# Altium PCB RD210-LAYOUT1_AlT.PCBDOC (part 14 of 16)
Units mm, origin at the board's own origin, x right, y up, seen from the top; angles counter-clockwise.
Board outline 330 x 300 mm, 6 copper layers (TOP, Mid-Layer 1, Mid-Layer 2, Mid-Layer 3, Mid-Layer 4, BOTTOM), stack 1.422 mm thick; 981 components, 463 nets, 2326 pads, 12534 vias.
Unrouted connection lines stored in the file: 6.
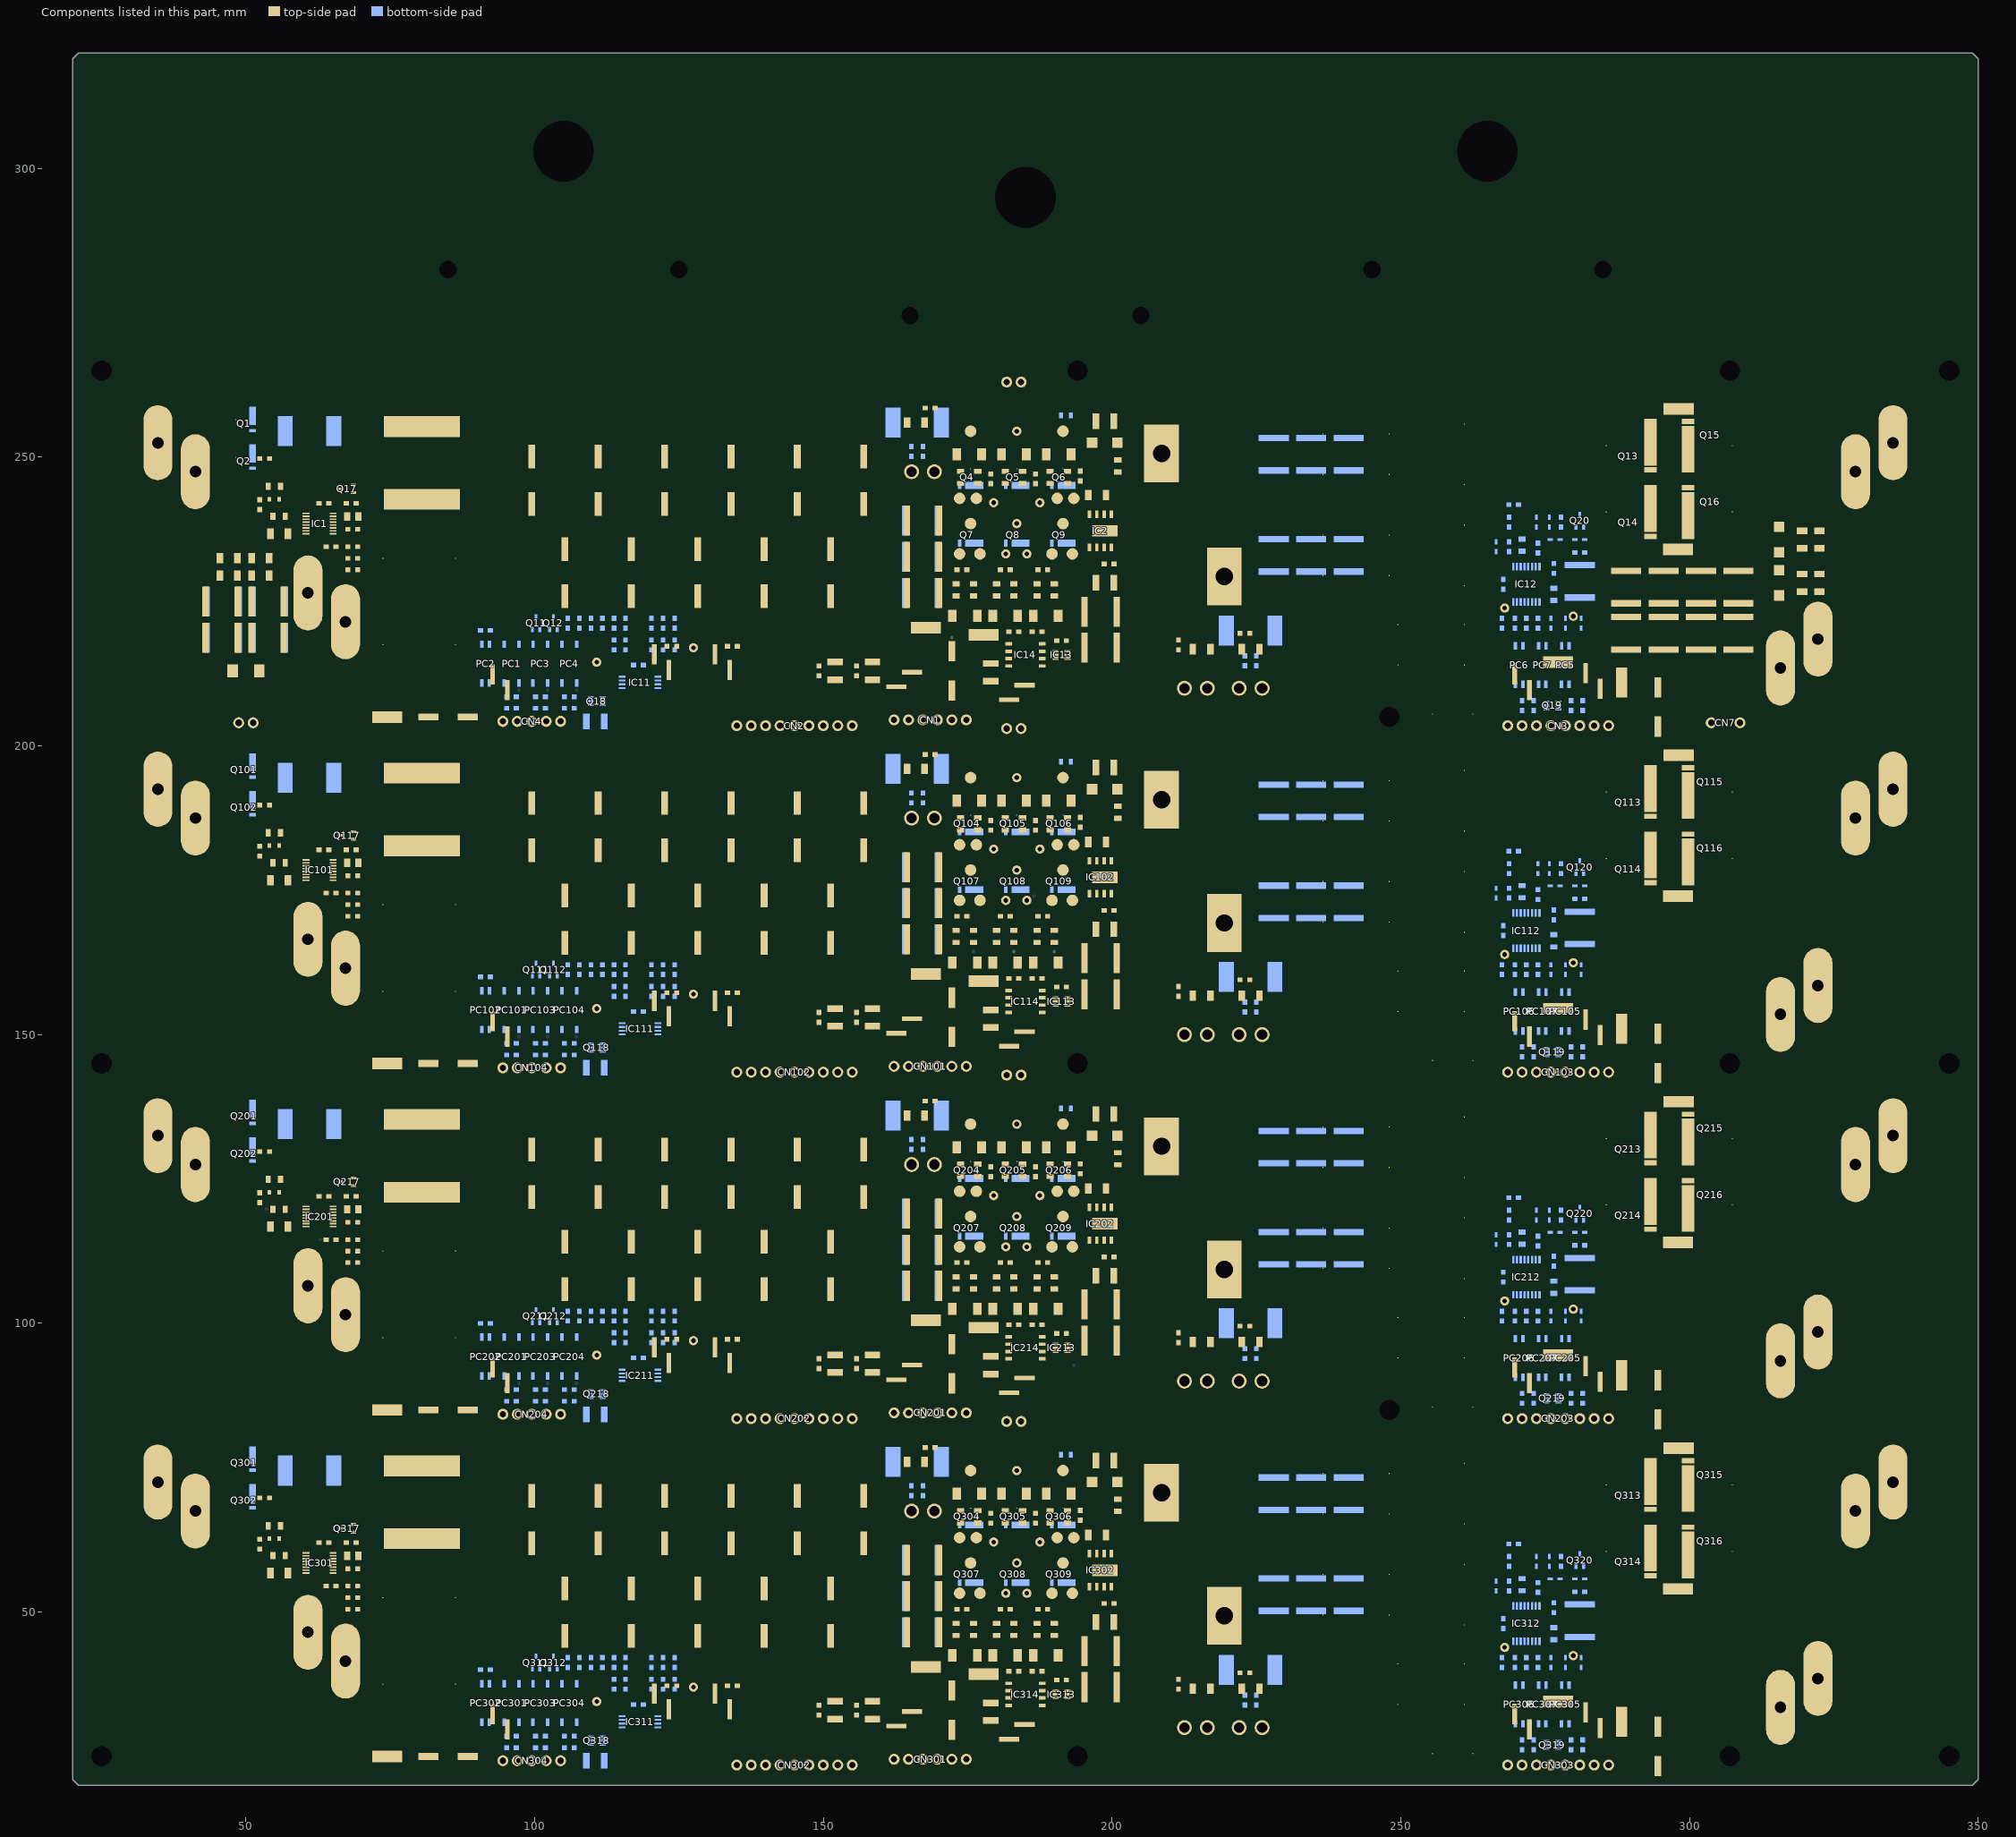
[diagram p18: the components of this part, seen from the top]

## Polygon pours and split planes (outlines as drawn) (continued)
no net on Bottom Overlay "BOTTOMOVERLAY797" (solid, pour order 0): 265.6,234.6 265.6,235.1 266.1,235.1 266.1,234.75 266.9,234.75 266.9,235.1 267.4,235.1 267.4,234.6
no net on Bottom Overlay "BOTTOMOVERLAY798" (solid, pour order 0): 281.1,234.85 281.1,236.65 281.6,236.65 281.6,236.15 281.25,236.15 281.25,235.35 281.6,235.35 281.6,234.85
no net on Bottom Overlay "BOTTOMOVERLAY799" (solid, pour order 0): 272.6,238.15 272.6,238.65 274.4,238.65 274.4,238.15 273.9,238.15 273.9,238.5 273.1,238.5 273.1,238.15
no net on Bottom Overlay "BOTTOMOVERLAY800" (solid, pour order 0): 265.6,174.6 265.6,175.1 266.1,175.1 266.1,174.75 266.9,174.75 266.9,175.1 267.4,175.1 267.4,174.6
no net on Bottom Overlay "BOTTOMOVERLAY801" (solid, pour order 0): 281.1,174.85 281.1,176.65 281.6,176.65 281.6,176.15 281.25,176.15 281.25,175.35 281.6,175.35 281.6,174.85
no net on Bottom Overlay "BOTTOMOVERLAY802" (solid, pour order 0): 272.85,178.15 272.85,178.65 274.65,178.65 274.65,178.15 274.15,178.15 274.15,178.5 273.35,178.5 273.35,178.15
no net on Bottom Overlay "BOTTOMOVERLAY803" (solid, pour order 0): 265.6,114.6 265.6,115.1 266.1,115.1 266.1,114.75 266.9,114.75 266.9,115.1 267.4,115.1 267.4,114.6
no net on Bottom Overlay "BOTTOMOVERLAY804" (solid, pour order 0): 281.1,114.85 281.1,116.65 281.6,116.65 281.6,116.15 281.25,116.15 281.25,115.35 281.6,115.35 281.6,114.85
no net on Bottom Overlay "BOTTOMOVERLAY805" (solid, pour order 0): 272.6,118.15 272.6,118.65 274.4,118.65 274.4,118.15 273.9,118.15 273.9,118.5 273.1,118.5 273.1,118.15
no net on Bottom Overlay "BOTTOMOVERLAY806" (solid, pour order 0): 265.6,54.6 265.6,55.1 266.1,55.1 266.1,54.75 266.9,54.75 266.9,55.1 267.4,55.1 267.4,54.6
no net on Bottom Overlay "BOTTOMOVERLAY807" (solid, pour order 0): 281.1,54.85 281.1,56.65 281.6,56.65 281.6,56.15 281.25,56.15 281.25,55.35 281.6,55.35 281.6,54.85
no net on Top Paste "TOPPASTE808" (solid, pour order 0): 282.85,248.45 282.85,251.75 285.35,251.75 285.35,248.45
no net on Top Paste "TOPPASTE809" (solid, pour order 0): 282.85,252.25 282.85,255.55 285.35,255.55 285.35,252.25
no net on Top Paste "TOPPASTE810" (solid, pour order 0): 285.85,252.25 285.85,255.55 288.65,255.55 288.65,252.25
no net on Top Paste "TOPPASTE811" (solid, pour order 0): 285.85,248.45 285.85,251.75 288.65,251.75 288.65,248.45
no net on Top Paste "TOPPASTE812" (solid, pour order 0): 292.15,248.55 292.15,249.45 294.35,249.45 294.35,248.55
no net on Top Paste "TOPPASTE813" (solid, pour order 0): 292.15,249.75 292.15,250.65 294.35,250.65 294.35,249.75
no net on Top Paste "TOPPASTE814" (solid, pour order 0): 292.15,250.95 292.15,251.85 294.35,251.85 294.35,250.95
no net on Top Paste "TOPPASTE815" (solid, pour order 0): 292.15,253.35 292.15,254.25 294.35,254.25 294.35,253.35
no net on Top Paste "TOPPASTE816" (solid, pour order 0): 292.15,254.55 292.15,255.45 294.35,255.45 294.35,254.55
no net on Top Paste "TOPPASTE817" (solid, pour order 0): 292.15,255.75 292.15,256.65 294.35,256.65 294.35,255.75
no net on Top Paste "TOPPASTE818" (solid, pour order 0): 282.85,236.95 282.85,240.25 285.35,240.25 285.35,236.95
no net on Top Paste "TOPPASTE819" (solid, pour order 0): 282.85,240.75 282.85,244.05 285.35,244.05 285.35,240.75
no net on Top Paste "TOPPASTE820" (solid, pour order 0): 285.85,240.75 285.85,244.05 288.65,244.05 288.65,240.75
no net on Top Paste "TOPPASTE821" (solid, pour order 0): 285.85,236.95 285.85,240.25 288.65,240.25 288.65,236.95
no net on Top Paste "TOPPASTE822" (solid, pour order 0): 292.15,237.05 292.15,237.95 294.35,237.95 294.35,237.05
no net on Top Paste "TOPPASTE823" (solid, pour order 0): 292.15,238.25 292.15,239.15 294.35,239.15 294.35,238.25
no net on Top Paste "TOPPASTE824" (solid, pour order 0): 292.15,239.45 292.15,240.35 294.35,240.35 294.35,239.45
no net on Top Paste "TOPPASTE825" (solid, pour order 0): 292.15,241.85 292.15,242.75 294.35,242.75 294.35,241.85
no net on Top Paste "TOPPASTE826" (solid, pour order 0): 292.15,243.05 292.15,243.95 294.35,243.95 294.35,243.05
no net on Top Paste "TOPPASTE827" (solid, pour order 0): 292.15,244.25 292.15,245.15 294.35,245.15 294.35,244.25
no net on Top Paste "TOPPASTE828" (solid, pour order 0): 307.65,252.25 307.65,255.55 310.15,255.55 310.15,252.25
no net on Top Paste "TOPPASTE829" (solid, pour order 0): 307.65,248.45 307.65,251.75 310.15,251.75 310.15,248.45
no net on Top Paste "TOPPASTE830" (solid, pour order 0): 304.35,248.45 304.35,251.75 307.15,251.75 307.15,248.45
no net on Top Paste "TOPPASTE831" (solid, pour order 0): 304.35,252.25 304.35,255.55 307.15,255.55 307.15,252.25
no net on Top Paste "TOPPASTE832" (solid, pour order 0): 298.65,254.55 298.65,255.45 300.85,255.45 300.85,254.55
no net on Top Paste "TOPPASTE833" (solid, pour order 0): 298.65,253.35 298.65,254.25 300.85,254.25 300.85,253.35
no net on Top Paste "TOPPASTE834" (solid, pour order 0): 298.65,252.15 298.65,253.05 300.85,253.05 300.85,252.15
no net on Top Paste "TOPPASTE835" (solid, pour order 0): 298.65,249.75 298.65,250.65 300.85,250.65 300.85,249.75
no net on Top Paste "TOPPASTE836" (solid, pour order 0): 298.65,248.55 298.65,249.45 300.85,249.45 300.85,248.55
no net on Top Paste "TOPPASTE837" (solid, pour order 0): 298.65,247.35 298.65,248.25 300.85,248.25 300.85,247.35
no net on Top Paste "TOPPASTE838" (solid, pour order 0): 307.65,240.75 307.65,244.05 310.15,244.05 310.15,240.75
no net on Top Paste "TOPPASTE839" (solid, pour order 0): 307.65,236.95 307.65,240.25 310.15,240.25 310.15,236.95
no net on Top Paste "TOPPASTE840" (solid, pour order 0): 304.35,236.95 304.35,240.25 307.15,240.25 307.15,236.95
no net on Top Paste "TOPPASTE841" (solid, pour order 0): 304.35,240.75 304.35,244.05 307.15,244.05 307.15,240.75
no net on Top Paste "TOPPASTE842" (solid, pour order 0): 298.65,243.05 298.65,243.95 300.85,243.95 300.85,243.05
no net on Top Paste "TOPPASTE843" (solid, pour order 0): 298.65,241.85 298.65,242.75 300.85,242.75 300.85,241.85
no net on Top Paste "TOPPASTE844" (solid, pour order 0): 298.65,240.65 298.65,241.55 300.85,241.55 300.85,240.65
no net on Top Paste "TOPPASTE845" (solid, pour order 0): 298.65,238.25 298.65,239.15 300.85,239.15 300.85,238.25
no net on Top Paste "TOPPASTE846" (solid, pour order 0): 298.65,237.05 298.65,237.95 300.85,237.95 300.85,237.05
no net on Top Paste "TOPPASTE847" (solid, pour order 0): 298.65,235.85 298.65,236.75 300.85,236.75 300.85,235.85
no net on Top Paste "TOPPASTE848" (solid, pour order 0): 282.85,176.95 282.85,180.25 285.35,180.25 285.35,176.95
no net on Top Paste "TOPPASTE849" (solid, pour order 0): 282.85,180.75 282.85,184.05 285.35,184.05 285.35,180.75
no net on Top Paste "TOPPASTE850" (solid, pour order 0): 285.85,180.75 285.85,184.05 288.65,184.05 288.65,180.75
no net on Top Paste "TOPPASTE851" (solid, pour order 0): 285.85,176.95 285.85,180.25 288.65,180.25 288.65,176.95
no net on Top Paste "TOPPASTE852" (solid, pour order 0): 292.15,177.05 292.15,177.95 294.35,177.95 294.35,177.05
no net on Top Paste "TOPPASTE853" (solid, pour order 0): 292.15,178.25 292.15,179.15 294.35,179.15 294.35,178.25
no net on Top Paste "TOPPASTE854" (solid, pour order 0): 292.15,179.45 292.15,180.35 294.35,180.35 294.35,179.45
no net on Top Paste "TOPPASTE855" (solid, pour order 0): 292.15,181.85 292.15,182.75 294.35,182.75 294.35,181.85
no net on Top Paste "TOPPASTE856" (solid, pour order 0): 292.15,183.05 292.15,183.95 294.35,183.95 294.35,183.05
no net on Top Paste "TOPPASTE857" (solid, pour order 0): 292.15,184.25 292.15,185.15 294.35,185.15 294.35,184.25
no net on Top Paste "TOPPASTE858" (solid, pour order 0): 282.85,188.45 282.85,191.75 285.35,191.75 285.35,188.45
no net on Top Paste "TOPPASTE859" (solid, pour order 0): 282.85,192.25 282.85,195.55 285.35,195.55 285.35,192.25
no net on Top Paste "TOPPASTE860" (solid, pour order 0): 285.85,192.25 285.85,195.55 288.65,195.55 288.65,192.25
no net on Top Paste "TOPPASTE861" (solid, pour order 0): 285.85,188.45 285.85,191.75 288.65,191.75 288.65,188.45
no net on Top Paste "TOPPASTE862" (solid, pour order 0): 292.15,188.55 292.15,189.45 294.35,189.45 294.35,188.55
no net on Top Paste "TOPPASTE863" (solid, pour order 0): 292.15,189.75 292.15,190.65 294.35,190.65 294.35,189.75
no net on Top Paste "TOPPASTE864" (solid, pour order 0): 292.15,190.95 292.15,191.85 294.35,191.85 294.35,190.95
no net on Top Paste "TOPPASTE865" (solid, pour order 0): 292.15,193.35 292.15,194.25 294.35,194.25 294.35,193.35
no net on Top Paste "TOPPASTE866" (solid, pour order 0): 292.15,194.55 292.15,195.45 294.35,195.45 294.35,194.55
no net on Top Paste "TOPPASTE867" (solid, pour order 0): 292.15,195.75 292.15,196.65 294.35,196.65 294.35,195.75
no net on Top Paste "TOPPASTE868" (solid, pour order 0): 307.65,180.75 307.65,184.05 310.15,184.05 310.15,180.75
no net on Top Paste "TOPPASTE869" (solid, pour order 0): 307.65,176.95 307.65,180.25 310.15,180.25 310.15,176.95
no net on Top Paste "TOPPASTE870" (solid, pour order 0): 304.35,176.95 304.35,180.25 307.15,180.25 307.15,176.95
no net on Top Paste "TOPPASTE871" (solid, pour order 0): 304.35,180.75 304.35,184.05 307.15,184.05 307.15,180.75
no net on Top Paste "TOPPASTE872" (solid, pour order 0): 298.65,183.05 298.65,183.95 300.85,183.95 300.85,183.05
no net on Top Paste "TOPPASTE873" (solid, pour order 0): 298.65,181.85 298.65,182.75 300.85,182.75 300.85,181.85
no net on Top Paste "TOPPASTE874" (solid, pour order 0): 298.65,180.65 298.65,181.55 300.85,181.55 300.85,180.65
no net on Top Paste "TOPPASTE875" (solid, pour order 0): 298.65,178.25 298.65,179.15 300.85,179.15 300.85,178.25
no net on Top Paste "TOPPASTE876" (solid, pour order 0): 298.65,177.05 298.65,177.95 300.85,177.95 300.85,177.05
no net on Top Paste "TOPPASTE877" (solid, pour order 0): 298.65,175.85 298.65,176.75 300.85,176.75 300.85,175.85
no net on Top Paste "TOPPASTE878" (solid, pour order 0): 307.65,192.25 307.65,195.55 310.15,195.55 310.15,192.25
no net on Top Paste "TOPPASTE879" (solid, pour order 0): 307.65,188.45 307.65,191.75 310.15,191.75 310.15,188.45
no net on Top Paste "TOPPASTE880" (solid, pour order 0): 304.35,188.45 304.35,191.75 307.15,191.75 307.15,188.45
no net on Top Paste "TOPPASTE881" (solid, pour order 0): 304.35,192.25 304.35,195.55 307.15,195.55 307.15,192.25
no net on Top Paste "TOPPASTE882" (solid, pour order 0): 298.65,194.55 298.65,195.45 300.85,195.45 300.85,194.55
no net on Top Paste "TOPPASTE883" (solid, pour order 0): 298.65,193.35 298.65,194.25 300.85,194.25 300.85,193.35
no net on Top Paste "TOPPASTE884" (solid, pour order 0): 298.65,192.15 298.65,193.05 300.85,193.05 300.85,192.15
no net on Top Paste "TOPPASTE885" (solid, pour order 0): 298.65,189.75 298.65,190.65 300.85,190.65 300.85,189.75
no net on Top Paste "TOPPASTE886" (solid, pour order 0): 298.65,188.55 298.65,189.45 300.85,189.45 300.85,188.55
no net on Top Paste "TOPPASTE887" (solid, pour order 0): 298.65,187.35 298.65,188.25 300.85,188.25 300.85,187.35
no net on Top Paste "TOPPASTE888" (solid, pour order 0): 282.85,116.95 282.85,120.25 285.35,120.25 285.35,116.95
no net on Top Paste "TOPPASTE889" (solid, pour order 0): 282.85,120.75 282.85,124.05 285.35,124.05 285.35,120.75
no net on Top Paste "TOPPASTE890" (solid, pour order 0): 285.85,120.75 285.85,124.05 288.65,124.05 288.65,120.75
no net on Top Paste "TOPPASTE891" (solid, pour order 0): 285.85,116.95 285.85,120.25 288.65,120.25 288.65,116.95
no net on Top Paste "TOPPASTE892" (solid, pour order 0): 292.15,117.05 292.15,117.95 294.35,117.95 294.35,117.05
no net on Top Paste "TOPPASTE893" (solid, pour order 0): 292.15,118.25 292.15,119.15 294.35,119.15 294.35,118.25
no net on Top Paste "TOPPASTE894" (solid, pour order 0): 292.15,119.45 292.15,120.35 294.35,120.35 294.35,119.45
no net on Top Paste "TOPPASTE895" (solid, pour order 0): 292.15,121.85 292.15,122.75 294.35,122.75 294.35,121.85
no net on Top Paste "TOPPASTE896" (solid, pour order 0): 292.15,123.05 292.15,123.95 294.35,123.95 294.35,123.05
no net on Top Paste "TOPPASTE897" (solid, pour order 0): 292.15,124.25 292.15,125.15 294.35,125.15 294.35,124.25
no net on Top Paste "TOPPASTE898" (solid, pour order 0): 282.85,128.45 282.85,131.75 285.35,131.75 285.35,128.45
no net on Top Paste "TOPPASTE899" (solid, pour order 0): 282.85,132.25 282.85,135.55 285.35,135.55 285.35,132.25
no net on Top Paste "TOPPASTE900" (solid, pour order 0): 285.85,132.25 285.85,135.55 288.65,135.55 288.65,132.25
no net on Top Paste "TOPPASTE901" (solid, pour order 0): 285.85,128.45 285.85,131.75 288.65,131.75 288.65,128.45
no net on Top Paste "TOPPASTE902" (solid, pour order 0): 292.15,128.55 292.15,129.45 294.35,129.45 294.35,128.55
no net on Top Paste "TOPPASTE903" (solid, pour order 0): 292.15,129.75 292.15,130.65 294.35,130.65 294.35,129.75
no net on Top Paste "TOPPASTE904" (solid, pour order 0): 292.15,130.95 292.15,131.85 294.35,131.85 294.35,130.95
no net on Top Paste "TOPPASTE905" (solid, pour order 0): 292.15,133.35 292.15,134.25 294.35,134.25 294.35,133.35
no net on Top Paste "TOPPASTE906" (solid, pour order 0): 292.15,134.55 292.15,135.45 294.35,135.45 294.35,134.55
no net on Top Paste "TOPPASTE907" (solid, pour order 0): 292.15,135.75 292.15,136.65 294.35,136.65 294.35,135.75
no net on Top Paste "TOPPASTE908" (solid, pour order 0): 307.65,120.75 307.65,124.05 310.15,124.05 310.15,120.75
no net on Top Paste "TOPPASTE909" (solid, pour order 0): 307.65,116.95 307.65,120.25 310.15,120.25 310.15,116.95
no net on Top Paste "TOPPASTE910" (solid, pour order 0): 304.35,116.95 304.35,120.25 307.15,120.25 307.15,116.95
no net on Top Paste "TOPPASTE911" (solid, pour order 0): 304.35,120.75 304.35,124.05 307.15,124.05 307.15,120.75
no net on Top Paste "TOPPASTE912" (solid, pour order 0): 298.65,123.05 298.65,123.95 300.85,123.95 300.85,123.05
no net on Top Paste "TOPPASTE913" (solid, pour order 0): 298.65,121.85 298.65,122.75 300.85,122.75 300.85,121.85
no net on Top Paste "TOPPASTE914" (solid, pour order 0): 298.65,120.65 298.65,121.55 300.85,121.55 300.85,120.65
no net on Top Paste "TOPPASTE915" (solid, pour order 0): 298.65,118.25 298.65,119.15 300.85,119.15 300.85,118.25
no net on Top Paste "TOPPASTE916" (solid, pour order 0): 298.65,117.05 298.65,117.95 300.85,117.95 300.85,117.05
no net on Top Paste "TOPPASTE917" (solid, pour order 0): 298.65,115.85 298.65,116.75 300.85,116.75 300.85,115.85
no net on Top Paste "TOPPASTE918" (solid, pour order 0): 307.65,132.25 307.65,135.55 310.15,135.55 310.15,132.25
no net on Top Paste "TOPPASTE919" (solid, pour order 0): 307.65,128.45 307.65,131.75 310.15,131.75 310.15,128.45
no net on Top Paste "TOPPASTE920" (solid, pour order 0): 304.35,128.45 304.35,131.75 307.15,131.75 307.15,128.45
no net on Top Paste "TOPPASTE921" (solid, pour order 0): 304.35,132.25 304.35,135.55 307.15,135.55 307.15,132.25
no net on Top Paste "TOPPASTE922" (solid, pour order 0): 298.65,134.55 298.65,135.45 300.85,135.45 300.85,134.55
no net on Top Paste "TOPPASTE923" (solid, pour order 0): 298.65,133.35 298.65,134.25 300.85,134.25 300.85,133.35
no net on Top Paste "TOPPASTE924" (solid, pour order 0): 298.65,132.15 298.65,133.05 300.85,133.05 300.85,132.15
no net on Top Paste "TOPPASTE925" (solid, pour order 0): 298.65,129.75 298.65,130.65 300.85,130.65 300.85,129.75
no net on Top Paste "TOPPASTE926" (solid, pour order 0): 298.65,128.55 298.65,129.45 300.85,129.45 300.85,128.55
no net on Top Paste "TOPPASTE927" (solid, pour order 0): 298.65,127.35 298.65,128.25 300.85,128.25 300.85,127.35
no net on Top Paste "TOPPASTE928" (solid, pour order 0): 282.85,56.95 282.85,60.25 285.35,60.25 285.35,56.95
no net on Top Paste "TOPPASTE929" (solid, pour order 0): 282.85,60.75 282.85,64.05 285.35,64.05 285.35,60.75
no net on Top Paste "TOPPASTE930" (solid, pour order 0): 285.85,60.75 285.85,64.05 288.65,64.05 288.65,60.75
no net on Top Paste "TOPPASTE931" (solid, pour order 0): 285.85,56.95 285.85,60.25 288.65,60.25 288.65,56.95
no net on Top Paste "TOPPASTE932" (solid, pour order 0): 292.15,57.05 292.15,57.95 294.35,57.95 294.35,57.05
no net on Top Paste "TOPPASTE933" (solid, pour order 0): 292.15,58.25 292.15,59.15 294.35,59.15 294.35,58.25
no net on Top Paste "TOPPASTE934" (solid, pour order 0): 292.15,59.45 292.15,60.35 294.35,60.35 294.35,59.45
no net on Top Paste "TOPPASTE935" (solid, pour order 0): 292.15,61.85 292.15,62.75 294.35,62.75 294.35,61.85
no net on Top Paste "TOPPASTE936" (solid, pour order 0): 292.15,63.05 292.15,63.95 294.35,63.95 294.35,63.05
no net on Top Paste "TOPPASTE937" (solid, pour order 0): 292.15,64.25 292.15,65.15 294.35,65.15 294.35,64.25
no net on Top Paste "TOPPASTE938" (solid, pour order 0): 282.85,68.45 282.85,71.75 285.35,71.75 285.35,68.45
no net on Top Paste "TOPPASTE939" (solid, pour order 0): 282.85,72.25 282.85,75.55 285.35,75.55 285.35,72.25
no net on Top Paste "TOPPASTE940" (solid, pour order 0): 285.85,72.25 285.85,75.55 288.65,75.55 288.65,72.25
no net on Top Paste "TOPPASTE941" (solid, pour order 0): 285.85,68.45 285.85,71.75 288.65,71.75 288.65,68.45
no net on Top Paste "TOPPASTE942" (solid, pour order 0): 292.15,68.55 292.15,69.45 294.35,69.45 294.35,68.55
no net on Top Paste "TOPPASTE943" (solid, pour order 0): 292.15,69.75 292.15,70.65 294.35,70.65 294.35,69.75
no net on Top Paste "TOPPASTE944" (solid, pour order 0): 292.15,70.95 292.15,71.85 294.35,71.85 294.35,70.95
no net on Top Paste "TOPPASTE945" (solid, pour order 0): 292.15,73.35 292.15,74.25 294.35,74.25 294.35,73.35
no net on Top Paste "TOPPASTE946" (solid, pour order 0): 292.15,74.55 292.15,75.45 294.35,75.45 294.35,74.55
no net on Top Paste "TOPPASTE947" (solid, pour order 0): 292.15,75.75 292.15,76.65 294.35,76.65 294.35,75.75
no net on Top Paste "TOPPASTE948" (solid, pour order 0): 307.65,60.75 307.65,64.05 310.15,64.05 310.15,60.75
no net on Top Paste "TOPPASTE949" (solid, pour order 0): 307.65,56.95 307.65,60.25 310.15,60.25 310.15,56.95
no net on Top Paste "TOPPASTE950" (solid, pour order 0): 304.35,56.95 304.35,60.25 307.15,60.25 307.15,56.95
no net on Top Paste "TOPPASTE951" (solid, pour order 0): 304.35,60.75 304.35,64.05 307.15,64.05 307.15,60.75
no net on Top Paste "TOPPASTE952" (solid, pour order 0): 298.65,63.05 298.65,63.95 300.85,63.95 300.85,63.05
no net on Top Paste "TOPPASTE953" (solid, pour order 0): 298.65,61.85 298.65,62.75 300.85,62.75 300.85,61.85
no net on Top Paste "TOPPASTE954" (solid, pour order 0): 298.65,60.65 298.65,61.55 300.85,61.55 300.85,60.65
no net on Top Paste "TOPPASTE955" (solid, pour order 0): 298.65,58.25 298.65,59.15 300.85,59.15 300.85,58.25
no net on Top Paste "TOPPASTE956" (solid, pour order 0): 298.65,57.05 298.65,57.95 300.85,57.95 300.85,57.05
no net on Top Paste "TOPPASTE957" (solid, pour order 0): 298.65,55.85 298.65,56.75 300.85,56.75 300.85,55.85
no net on Top Paste "TOPPASTE958" (solid, pour order 0): 307.65,72.25 307.65,75.55 310.15,75.55 310.15,72.25
no net on Top Paste "TOPPASTE959" (solid, pour order 0): 307.65,68.45 307.65,71.75 310.15,71.75 310.15,68.45
no net on Top Paste "TOPPASTE960" (solid, pour order 0): 304.35,68.45 304.35,71.75 307.15,71.75 307.15,68.45
no net on Top Paste "TOPPASTE961" (solid, pour order 0): 304.35,72.25 304.35,75.55 307.15,75.55 307.15,72.25
no net on Top Paste "TOPPASTE962" (solid, pour order 0): 298.65,74.55 298.65,75.45 300.85,75.45 300.85,74.55
no net on Top Paste "TOPPASTE963" (solid, pour order 0): 298.65,73.35 298.65,74.25 300.85,74.25 300.85,73.35
no net on Top Paste "TOPPASTE964" (solid, pour order 0): 298.65,72.15 298.65,73.05 300.85,73.05 300.85,72.15
no net on Top Paste "TOPPASTE965" (solid, pour order 0): 298.65,69.75 298.65,70.65 300.85,70.65 300.85,69.75
no net on Top Paste "TOPPASTE966" (solid, pour order 0): 298.65,68.55 298.65,69.45 300.85,69.45 300.85,68.55
no net on Top Paste "TOPPASTE967" (solid, pour order 0): 298.65,67.35 298.65,68.25 300.85,68.25 300.85,67.35
no net on Top Paste "TOPPASTE968" (solid, pour order 0): 198.1,236.35 198.1,237.15 199.35,237.15 199.35,236.35
no net on Top Paste "TOPPASTE969" (solid, pour order 0): 196.65,236.35 196.65,237.15 197.9,237.15 197.9,236.35
no net on Top Paste "TOPPASTE970" (solid, pour order 0): 196.65,237.35 196.65,238.15 197.9,238.15 197.9,237.35
no net on Top Paste "TOPPASTE971" (solid, pour order 0): 198.1,237.35 198.1,238.15 199.35,238.15 199.35,237.35
no net on Top Paste "TOPPASTE972" (solid, pour order 0): 198.1,176.35 198.1,177.15 199.35,177.15 199.35,176.35
no net on Top Paste "TOPPASTE973" (solid, pour order 0): 196.65,176.35 196.65,177.15 197.9,177.15 197.9,176.35
no net on Top Paste "TOPPASTE974" (solid, pour order 0): 196.65,177.35 196.65,178.15 197.9,178.15 197.9,177.35
no net on Top Paste "TOPPASTE975" (solid, pour order 0): 198.1,177.35 198.1,178.15 199.35,178.15 199.35,177.35
no net on Top Paste "TOPPASTE976" (solid, pour order 0): 198.1,116.35 198.1,117.15 199.35,117.15 199.35,116.35
no net on Top Paste "TOPPASTE977" (solid, pour order 0): 196.65,116.35 196.65,117.15 197.9,117.15 197.9,116.35
no net on Top Paste "TOPPASTE978" (solid, pour order 0): 196.65,117.35 196.65,118.15 197.9,118.15 197.9,117.35
no net on Top Paste "TOPPASTE979" (solid, pour order 0): 198.1,117.35 198.1,118.15 199.35,118.15 199.35,117.35
no net on Top Paste "TOPPASTE980" (solid, pour order 0): 198.1,56.35 198.1,57.15 199.35,57.15 199.35,56.35
no net on Top Paste "TOPPASTE981" (solid, pour order 0): 196.65,56.35 196.65,57.15 197.9,57.15 197.9,56.35
no net on Top Paste "TOPPASTE982" (solid, pour order 0): 196.65,57.35 196.65,58.15 197.9,58.15 197.9,57.35
no net on Top Paste "TOPPASTE983" (solid, pour order 0): 198.1,57.35 198.1,58.15 199.35,58.15 199.35,57.35
no net on Bottom Paste "BOTTOMPASTE984" (solid, pour order 0): 174.565,244.5 174.565,245.7 175.165,245.7 175.165,244.5
no net on Bottom Paste "BOTTOMPASTE985" (solid, pour order 0): 177.105,244.5 177.105,245.7 177.705,245.7 177.705,244.5
no net on Bottom Paste "BOTTOMPASTE986" (solid, pour order 0): 173.295,250.3 173.295,251.5 173.895,251.5 173.895,250.3
no net on Bottom Paste "BOTTOMPASTE987" (solid, pour order 0): 174.565,250.3 174.565,251.5 175.165,251.5 175.165,250.3
no net on Bottom Paste "BOTTOMPASTE988" (solid, pour order 0): 175.835,250.3 175.835,251.5 176.435,251.5 176.435,250.3
no net on Bottom Paste "BOTTOMPASTE989" (solid, pour order 0): 177.105,250.3 177.105,251.5 177.705,251.5 177.705,250.3
no net on Bottom Paste "BOTTOMPASTE990" (solid, pour order 0): 175.7,247.05 175.7,248.25 177.355,248.25 177.355,247.05
no net on Bottom Paste "BOTTOMPASTE991" (solid, pour order 0): 175.7,248.65 175.7,249.85 177.355,249.85 177.355,248.65
no net on Bottom Paste "BOTTOMPASTE992" (solid, pour order 0): 173.645,248.65 173.645,249.85 175.3,249.85 175.3,248.65
no net on Bottom Paste "BOTTOMPASTE993" (solid, pour order 0): 173.645,247.05 173.645,248.25 175.3,248.25 175.3,247.05
no net on Bottom Paste "BOTTOMPASTE994" (solid, pour order 0): 174.565,234.5 174.565,235.7 175.165,235.7 175.165,234.5
no net on Bottom Paste "BOTTOMPASTE995" (solid, pour order 0): 177.105,234.5 177.105,235.7 177.705,235.7 177.705,234.5
no net on Bottom Paste "BOTTOMPASTE996" (solid, pour order 0): 173.295,240.3 173.295,241.5 173.895,241.5 173.895,240.3
no net on Bottom Paste "BOTTOMPASTE997" (solid, pour order 0): 174.565,240.3 174.565,241.5 175.165,241.5 175.165,240.3
no net on Bottom Paste "BOTTOMPASTE998" (solid, pour order 0): 175.835,240.3 175.835,241.5 176.435,241.5 176.435,240.3
no net on Bottom Paste "BOTTOMPASTE999" (solid, pour order 0): 177.105,240.3 177.105,241.5 177.705,241.5 177.705,240.3
no net on Bottom Paste "BOTTOMPASTE1000" (solid, pour order 0): 175.7,237.05 175.7,238.25 177.355,238.25 177.355,237.05
no net on Bottom Paste "BOTTOMPASTE1001" (solid, pour order 0): 175.7,238.65 175.7,239.85 177.355,239.85 177.355,238.65
no net on Bottom Paste "BOTTOMPASTE1002" (solid, pour order 0): 173.645,238.65 173.645,239.85 175.3,239.85 175.3,238.65
no net on Bottom Paste "BOTTOMPASTE1003" (solid, pour order 0): 173.645,237.05 173.645,238.25 175.3,238.25 175.3,237.05
no net on Bottom Paste "BOTTOMPASTE1004" (solid, pour order 0): 182.565,244.5 182.565,245.7 183.165,245.7 183.165,244.5
no net on Bottom Paste "BOTTOMPASTE1005" (solid, pour order 0): 185.105,244.5 185.105,245.7 185.705,245.7 185.705,244.5
no net on Bottom Paste "BOTTOMPASTE1006" (solid, pour order 0): 181.295,250.3 181.295,251.5 181.895,251.5 181.895,250.3
no net on Bottom Paste "BOTTOMPASTE1007" (solid, pour order 0): 182.565,250.3 182.565,251.5 183.165,251.5 183.165,250.3
no net on Bottom Paste "BOTTOMPASTE1008" (solid, pour order 0): 183.835,250.3 183.835,251.5 184.435,251.5 184.435,250.3
no net on Bottom Paste "BOTTOMPASTE1009" (solid, pour order 0): 185.105,250.3 185.105,251.5 185.705,251.5 185.705,250.3
no net on Bottom Paste "BOTTOMPASTE1010" (solid, pour order 0): 183.7,247.05 183.7,248.25 185.355,248.25 185.355,247.05
no net on Bottom Paste "BOTTOMPASTE1011" (solid, pour order 0): 183.7,248.65 183.7,249.85 185.355,249.85 185.355,248.65
no net on Bottom Paste "BOTTOMPASTE1012" (solid, pour order 0): 181.645,248.65 181.645,249.85 183.3,249.85 183.3,248.65
no net on Bottom Paste "BOTTOMPASTE1013" (solid, pour order 0): 181.645,247.05 181.645,248.25 183.3,248.25 183.3,247.05
no net on Bottom Paste "BOTTOMPASTE1014" (solid, pour order 0): 182.565,234.5 182.565,235.7 183.165,235.7 183.165,234.5
no net on Bottom Paste "BOTTOMPASTE1015" (solid, pour order 0): 185.105,234.5 185.105,235.7 185.705,235.7 185.705,234.5
no net on Bottom Paste "BOTTOMPASTE1016" (solid, pour order 0): 181.295,240.3 181.295,241.5 181.895,241.5 181.895,240.3
no net on Bottom Paste "BOTTOMPASTE1017" (solid, pour order 0): 182.565,240.3 182.565,241.5 183.165,241.5 183.165,240.3
no net on Bottom Paste "BOTTOMPASTE1018" (solid, pour order 0): 183.835,240.3 183.835,241.5 184.435,241.5 184.435,240.3
no net on Bottom Paste "BOTTOMPASTE1019" (solid, pour order 0): 185.105,240.3 185.105,241.5 185.705,241.5 185.705,240.3
no net on Bottom Paste "BOTTOMPASTE1020" (solid, pour order 0): 183.7,237.05 183.7,238.25 185.355,238.25 185.355,237.05
no net on Bottom Paste "BOTTOMPASTE1021" (solid, pour order 0): 183.7,238.65 183.7,239.85 185.355,239.85 185.355,238.65
no net on Bottom Paste "BOTTOMPASTE1022" (solid, pour order 0): 181.645,238.65 181.645,239.85 183.3,239.85 183.3,238.65
no net on Bottom Paste "BOTTOMPASTE1023" (solid, pour order 0): 181.645,237.05 181.645,238.25 183.3,238.25 183.3,237.05
no net on Bottom Paste "BOTTOMPASTE1024" (solid, pour order 0): 190.565,244.5 190.565,245.7 191.165,245.7 191.165,244.5
no net on Bottom Paste "BOTTOMPASTE1025" (solid, pour order 0): 193.105,244.5 193.105,245.7 193.705,245.7 193.705,244.5
no net on Bottom Paste "BOTTOMPASTE1026" (solid, pour order 0): 189.295,250.3 189.295,251.5 189.895,251.5 189.895,250.3
no net on Bottom Paste "BOTTOMPASTE1027" (solid, pour order 0): 190.565,250.3 190.565,251.5 191.165,251.5 191.165,250.3
no net on Bottom Paste "BOTTOMPASTE1028" (solid, pour order 0): 191.835,250.3 191.835,251.5 192.435,251.5 192.435,250.3
no net on Bottom Paste "BOTTOMPASTE1029" (solid, pour order 0): 193.105,250.3 193.105,251.5 193.705,251.5 193.705,250.3
no net on Bottom Paste "BOTTOMPASTE1030" (solid, pour order 0): 191.7,247.05 191.7,248.25 193.355,248.25 193.355,247.05
no net on Bottom Paste "BOTTOMPASTE1031" (solid, pour order 0): 191.7,248.65 191.7,249.85 193.355,249.85 193.355,248.65
no net on Bottom Paste "BOTTOMPASTE1032" (solid, pour order 0): 189.645,248.65 189.645,249.85 191.3,249.85 191.3,248.65
no net on Bottom Paste "BOTTOMPASTE1033" (solid, pour order 0): 189.645,247.05 189.645,248.25 191.3,248.25 191.3,247.05
no net on Bottom Paste "BOTTOMPASTE1034" (solid, pour order 0): 190.565,234.5 190.565,235.7 191.165,235.7 191.165,234.5
no net on Bottom Paste "BOTTOMPASTE1035" (solid, pour order 0): 193.105,234.5 193.105,235.7 193.705,235.7 193.705,234.5
no net on Bottom Paste "BOTTOMPASTE1036" (solid, pour order 0): 189.295,240.3 189.295,241.5 189.895,241.5 189.895,240.3
no net on Bottom Paste "BOTTOMPASTE1037" (solid, pour order 0): 190.565,240.3 190.565,241.5 191.165,241.5 191.165,240.3
no net on Bottom Paste "BOTTOMPASTE1038" (solid, pour order 0): 191.835,240.3 191.835,241.5 192.435,241.5 192.435,240.3
no net on Bottom Paste "BOTTOMPASTE1039" (solid, pour order 0): 193.105,240.3 193.105,241.5 193.705,241.5 193.705,240.3
no net on Bottom Paste "BOTTOMPASTE1040" (solid, pour order 0): 191.7,237.05 191.7,238.25 193.355,238.25 193.355,237.05
no net on Bottom Paste "BOTTOMPASTE1041" (solid, pour order 0): 191.7,238.65 191.7,239.85 193.355,239.85 193.355,238.65
no net on Bottom Paste "BOTTOMPASTE1042" (solid, pour order 0): 189.645,238.65 189.645,239.85 191.3,239.85 191.3,238.65
no net on Bottom Paste "BOTTOMPASTE1043" (solid, pour order 0): 189.645,237.05 189.645,238.25 191.3,238.25 191.3,237.05
no net on Bottom Paste "BOTTOMPASTE1044" (solid, pour order 0): 50.55,135.565 50.55,136.165 51.75,136.165 51.75,135.565
no net on Bottom Paste "BOTTOMPASTE1045" (solid, pour order 0): 50.55,138.105 50.55,138.705 51.75,138.705 51.75,138.105
no net on Bottom Paste "BOTTOMPASTE1046" (solid, pour order 0): 44.75,134.295 44.75,134.895 45.95,134.895 45.95,134.295
no net on Bottom Paste "BOTTOMPASTE1047" (solid, pour order 0): 44.75,135.565 44.75,136.165 45.95,136.165 45.95,135.565
no net on Bottom Paste "BOTTOMPASTE1048" (solid, pour order 0): 44.75,136.835 44.75,137.435 45.95,137.435 45.95,136.835
no net on Bottom Paste "BOTTOMPASTE1049" (solid, pour order 0): 44.75,138.105 44.75,138.705 45.95,138.705 45.95,138.105
no net on Bottom Paste "BOTTOMPASTE1050" (solid, pour order 0): 48,136.7 48,138.355 49.2,138.355 49.2,136.7
no net on Bottom Paste "BOTTOMPASTE1051" (solid, pour order 0): 46.4,136.7 46.4,138.355 47.6,138.355 47.6,136.7
no net on Bottom Paste "BOTTOMPASTE1052" (solid, pour order 0): 46.4,134.645 46.4,136.3 47.6,136.3 47.6,134.645
no net on Bottom Paste "BOTTOMPASTE1053" (solid, pour order 0): 48,134.645 48,136.3 49.2,136.3 49.2,134.645
no net on Bottom Paste "BOTTOMPASTE1054" (solid, pour order 0): 50.55,129.065 50.55,129.665 51.75,129.665 51.75,129.065
no net on Bottom Paste "BOTTOMPASTE1055" (solid, pour order 0): 50.55,131.605 50.55,132.205 51.75,132.205 51.75,131.605
no net on Bottom Paste "BOTTOMPASTE1056" (solid, pour order 0): 44.75,127.795 44.75,128.395 45.95,128.395 45.95,127.795
no net on Bottom Paste "BOTTOMPASTE1057" (solid, pour order 0): 44.75,129.065 44.75,129.665 45.95,129.665 45.95,129.065
no net on Bottom Paste "BOTTOMPASTE1058" (solid, pour order 0): 44.75,130.335 44.75,130.935 45.95,130.935 45.95,130.335
no net on Bottom Paste "BOTTOMPASTE1059" (solid, pour order 0): 44.75,131.605 44.75,132.205 45.95,132.205 45.95,131.605
no net on Bottom Paste "BOTTOMPASTE1060" (solid, pour order 0): 48,130.2 48,131.855 49.2,131.855 49.2,130.2
no net on Bottom Paste "BOTTOMPASTE1061" (solid, pour order 0): 46.4,130.2 46.4,131.855 47.6,131.855 47.6,130.2
no net on Bottom Paste "BOTTOMPASTE1062" (solid, pour order 0): 46.4,128.145 46.4,129.8 47.6,129.8 47.6,128.145
no net on Bottom Paste "BOTTOMPASTE1063" (solid, pour order 0): 48,128.145 48,129.8 49.2,129.8 49.2,128.145
no net on Bottom Paste "BOTTOMPASTE1064" (solid, pour order 0): 174.565,124.5 174.565,125.7 175.165,125.7 175.165,124.5
no net on Bottom Paste "BOTTOMPASTE1065" (solid, pour order 0): 177.105,124.5 177.105,125.7 177.705,125.7 177.705,124.5
no net on Bottom Paste "BOTTOMPASTE1066" (solid, pour order 0): 173.295,130.3 173.295,131.5 173.895,131.5 173.895,130.3
no net on Bottom Paste "BOTTOMPASTE1067" (solid, pour order 0): 174.565,130.3 174.565,131.5 175.165,131.5 175.165,130.3
no net on Bottom Paste "BOTTOMPASTE1068" (solid, pour order 0): 175.835,130.3 175.835,131.5 176.435,131.5 176.435,130.3
no net on Bottom Paste "BOTTOMPASTE1069" (solid, pour order 0): 177.105,130.3 177.105,131.5 177.705,131.5 177.705,130.3
no net on Bottom Paste "BOTTOMPASTE1070" (solid, pour order 0): 175.7,127.05 175.7,128.25 177.355,128.25 177.355,127.05
no net on Bottom Paste "BOTTOMPASTE1071" (solid, pour order 0): 175.7,128.65 175.7,129.85 177.355,129.85 177.355,128.65
no net on Bottom Paste "BOTTOMPASTE1072" (solid, pour order 0): 173.645,128.65 173.645,129.85 175.3,129.85 175.3,128.65
no net on Bottom Paste "BOTTOMPASTE1073" (solid, pour order 0): 173.645,127.05 173.645,128.25 175.3,128.25 175.3,127.05
no net on Bottom Paste "BOTTOMPASTE1074" (solid, pour order 0): 182.565,124.5 182.565,125.7 183.165,125.7 183.165,124.5
no net on Bottom Paste "BOTTOMPASTE1075" (solid, pour order 0): 185.105,124.5 185.105,125.7 185.705,125.7 185.705,124.5
no net on Bottom Paste "BOTTOMPASTE1076" (solid, pour order 0): 181.295,130.3 181.295,131.5 181.895,131.5 181.895,130.3
no net on Bottom Paste "BOTTOMPASTE1077" (solid, pour order 0): 182.565,130.3 182.565,131.5 183.165,131.5 183.165,130.3
no net on Bottom Paste "BOTTOMPASTE1078" (solid, pour order 0): 183.835,130.3 183.835,131.5 184.435,131.5 184.435,130.3
no net on Bottom Paste "BOTTOMPASTE1079" (solid, pour order 0): 185.105,130.3 185.105,131.5 185.705,131.5 185.705,130.3
no net on Bottom Paste "BOTTOMPASTE1080" (solid, pour order 0): 183.7,127.05 183.7,128.25 185.355,128.25 185.355,127.05
no net on Bottom Paste "BOTTOMPASTE1081" (solid, pour order 0): 183.7,128.65 183.7,129.85 185.355,129.85 185.355,128.65
no net on Bottom Paste "BOTTOMPASTE1082" (solid, pour order 0): 181.645,128.65 181.645,129.85 183.3,129.85 183.3,128.65
no net on Bottom Paste "BOTTOMPASTE1083" (solid, pour order 0): 181.645,127.05 181.645,128.25 183.3,128.25 183.3,127.05
no net on Bottom Paste "BOTTOMPASTE1084" (solid, pour order 0): 190.565,124.5 190.565,125.7 191.165,125.7 191.165,124.5
no net on Bottom Paste "BOTTOMPASTE1085" (solid, pour order 0): 193.105,124.5 193.105,125.7 193.705,125.7 193.705,124.5
no net on Bottom Paste "BOTTOMPASTE1086" (solid, pour order 0): 189.295,130.3 189.295,131.5 189.895,131.5 189.895,130.3
no net on Bottom Paste "BOTTOMPASTE1087" (solid, pour order 0): 190.565,130.3 190.565,131.5 191.165,131.5 191.165,130.3
no net on Bottom Paste "BOTTOMPASTE1088" (solid, pour order 0): 191.835,130.3 191.835,131.5 192.435,131.5 192.435,130.3
no net on Bottom Paste "BOTTOMPASTE1089" (solid, pour order 0): 193.105,130.3 193.105,131.5 193.705,131.5 193.705,130.3
no net on Bottom Paste "BOTTOMPASTE1090" (solid, pour order 0): 191.7,127.05 191.7,128.25 193.355,128.25 193.355,127.05
no net on Bottom Paste "BOTTOMPASTE1091" (solid, pour order 0): 191.7,128.65 191.7,129.85 193.355,129.85 193.355,128.65
no net on Bottom Paste "BOTTOMPASTE1092" (solid, pour order 0): 189.645,128.65 189.645,129.85 191.3,129.85 191.3,128.65
no net on Bottom Paste "BOTTOMPASTE1093" (solid, pour order 0): 189.645,127.05 189.645,128.25 191.3,128.25 191.3,127.05
no net on Bottom Paste "BOTTOMPASTE1094" (solid, pour order 0): 174.565,114.5 174.565,115.7 175.165,115.7 175.165,114.5
no net on Bottom Paste "BOTTOMPASTE1095" (solid, pour order 0): 177.105,114.5 177.105,115.7 177.705,115.7 177.705,114.5
no net on Bottom Paste "BOTTOMPASTE1096" (solid, pour order 0): 173.295,120.3 173.295,121.5 173.895,121.5 173.895,120.3
no net on Bottom Paste "BOTTOMPASTE1097" (solid, pour order 0): 174.565,120.3 174.565,121.5 175.165,121.5 175.165,120.3
no net on Bottom Paste "BOTTOMPASTE1098" (solid, pour order 0): 175.835,120.3 175.835,121.5 176.435,121.5 176.435,120.3
no net on Bottom Paste "BOTTOMPASTE1099" (solid, pour order 0): 177.105,120.3 177.105,121.5 177.705,121.5 177.705,120.3
no net on Bottom Paste "BOTTOMPASTE1100" (solid, pour order 0): 175.7,117.05 175.7,118.25 177.355,118.25 177.355,117.05
no net on Bottom Paste "BOTTOMPASTE1101" (solid, pour order 0): 175.7,118.65 175.7,119.85 177.355,119.85 177.355,118.65
no net on Bottom Paste "BOTTOMPASTE1102" (solid, pour order 0): 173.645,118.65 173.645,119.85 175.3,119.85 175.3,118.65
no net on Bottom Paste "BOTTOMPASTE1103" (solid, pour order 0): 173.645,117.05 173.645,118.25 175.3,118.25 175.3,117.05
no net on Bottom Paste "BOTTOMPASTE1104" (solid, pour order 0): 182.565,114.5 182.565,115.7 183.165,115.7 183.165,114.5
no net on Bottom Paste "BOTTOMPASTE1105" (solid, pour order 0): 185.105,114.5 185.105,115.7 185.705,115.7 185.705,114.5
no net on Bottom Paste "BOTTOMPASTE1106" (solid, pour order 0): 181.295,120.3 181.295,121.5 181.895,121.5 181.895,120.3
no net on Bottom Paste "BOTTOMPASTE1107" (solid, pour order 0): 182.565,120.3 182.565,121.5 183.165,121.5 183.165,120.3
no net on Bottom Paste "BOTTOMPASTE1108" (solid, pour order 0): 183.835,120.3 183.835,121.5 184.435,121.5 184.435,120.3
no net on Bottom Paste "BOTTOMPASTE1109" (solid, pour order 0): 185.105,120.3 185.105,121.5 185.705,121.5 185.705,120.3
no net on Bottom Paste "BOTTOMPASTE1110" (solid, pour order 0): 183.7,117.05 183.7,118.25 185.355,118.25 185.355,117.05
no net on Bottom Paste "BOTTOMPASTE1111" (solid, pour order 0): 183.7,118.65 183.7,119.85 185.355,119.85 185.355,118.65
no net on Bottom Paste "BOTTOMPASTE1112" (solid, pour order 0): 181.645,118.65 181.645,119.85 183.3,119.85 183.3,118.65
no net on Bottom Paste "BOTTOMPASTE1113" (solid, pour order 0): 181.645,117.05 181.645,118.25 183.3,118.25 183.3,117.05
no net on Bottom Paste "BOTTOMPASTE1114" (solid, pour order 0): 190.565,114.5 190.565,115.7 191.165,115.7 191.165,114.5
no net on Bottom Paste "BOTTOMPASTE1115" (solid, pour order 0): 193.105,114.5 193.105,115.7 193.705,115.7 193.705,114.5
no net on Bottom Paste "BOTTOMPASTE1116" (solid, pour order 0): 189.295,120.3 189.295,121.5 189.895,121.5 189.895,120.3
no net on Bottom Paste "BOTTOMPASTE1117" (solid, pour order 0): 190.565,120.3 190.565,121.5 191.165,121.5 191.165,120.3
no net on Bottom Paste "BOTTOMPASTE1118" (solid, pour order 0): 191.835,120.3 191.835,121.5 192.435,121.5 192.435,120.3
no net on Bottom Paste "BOTTOMPASTE1119" (solid, pour order 0): 193.105,120.3 193.105,121.5 193.705,121.5 193.705,120.3
no net on Bottom Paste "BOTTOMPASTE1120" (solid, pour order 0): 191.7,117.05 191.7,118.25 193.355,118.25 193.355,117.05
no net on Bottom Paste "BOTTOMPASTE1121" (solid, pour order 0): 191.7,118.65 191.7,119.85 193.355,119.85 193.355,118.65
no net on Bottom Paste "BOTTOMPASTE1122" (solid, pour order 0): 189.645,118.65 189.645,119.85 191.3,119.85 191.3,118.65
no net on Bottom Paste "BOTTOMPASTE1123" (solid, pour order 0): 189.645,117.05 189.645,118.25 191.3,118.25 191.3,117.05
no net on Bottom Paste "BOTTOMPASTE1124" (solid, pour order 0): 50.55,75.565 50.55,76.165 51.75,76.165 51.75,75.565
no net on Bottom Paste "BOTTOMPASTE1125" (solid, pour order 0): 50.55,78.105 50.55,78.705 51.75,78.705 51.75,78.105
no net on Bottom Paste "BOTTOMPASTE1126" (solid, pour order 0): 44.75,74.295 44.75,74.895 45.95,74.895 45.95,74.295
no net on Bottom Paste "BOTTOMPASTE1127" (solid, pour order 0): 44.75,75.565 44.75,76.165 45.95,76.165 45.95,75.565
no net on Bottom Paste "BOTTOMPASTE1128" (solid, pour order 0): 44.75,76.835 44.75,77.435 45.95,77.435 45.95,76.835
no net on Bottom Paste "BOTTOMPASTE1129" (solid, pour order 0): 44.75,78.105 44.75,78.705 45.95,78.705 45.95,78.105
no net on Bottom Paste "BOTTOMPASTE1130" (solid, pour order 0): 48,76.7 48,78.355 49.2,78.355 49.2,76.7
no net on Bottom Paste "BOTTOMPASTE1131" (solid, pour order 0): 46.4,76.7 46.4,78.355 47.6,78.355 47.6,76.7
no net on Bottom Paste "BOTTOMPASTE1132" (solid, pour order 0): 46.4,74.645 46.4,76.3 47.6,76.3 47.6,74.645
no net on Bottom Paste "BOTTOMPASTE1133" (solid, pour order 0): 48,74.645 48,76.3 49.2,76.3 49.2,74.645
no net on Bottom Paste "BOTTOMPASTE1134" (solid, pour order 0): 50.55,69.065 50.55,69.665 51.75,69.665 51.75,69.065
no net on Bottom Paste "BOTTOMPASTE1135" (solid, pour order 0): 50.55,71.605 50.55,72.205 51.75,72.205 51.75,71.605
no net on Bottom Paste "BOTTOMPASTE1136" (solid, pour order 0): 44.75,67.795 44.75,68.395 45.95,68.395 45.95,67.795
no net on Bottom Paste "BOTTOMPASTE1137" (solid, pour order 0): 44.75,69.065 44.75,69.665 45.95,69.665 45.95,69.065
no net on Bottom Paste "BOTTOMPASTE1138" (solid, pour order 0): 44.75,70.335 44.75,70.935 45.95,70.935 45.95,70.335
no net on Bottom Paste "BOTTOMPASTE1139" (solid, pour order 0): 44.75,71.605 44.75,72.205 45.95,72.205 45.95,71.605
no net on Bottom Paste "BOTTOMPASTE1140" (solid, pour order 0): 48,70.2 48,71.855 49.2,71.855 49.2,70.2
no net on Bottom Paste "BOTTOMPASTE1141" (solid, pour order 0): 46.4,70.2 46.4,71.855 47.6,71.855 47.6,70.2
no net on Bottom Paste "BOTTOMPASTE1142" (solid, pour order 0): 46.4,68.145 46.4,69.8 47.6,69.8 47.6,68.145
no net on Bottom Paste "BOTTOMPASTE1143" (solid, pour order 0): 48,68.145 48,69.8 49.2,69.8 49.2,68.145
no net on Bottom Paste "BOTTOMPASTE1144" (solid, pour order 0): 174.565,64.5 174.565,65.7 175.165,65.7 175.165,64.5
no net on Bottom Paste "BOTTOMPASTE1145" (solid, pour order 0): 177.105,64.5 177.105,65.7 177.705,65.7 177.705,64.5
no net on Bottom Paste "BOTTOMPASTE1146" (solid, pour order 0): 173.295,70.3 173.295,71.5 173.895,71.5 173.895,70.3
no net on Bottom Paste "BOTTOMPASTE1147" (solid, pour order 0): 174.565,70.3 174.565,71.5 175.165,71.5 175.165,70.3
no net on Bottom Paste "BOTTOMPASTE1148" (solid, pour order 0): 175.835,70.3 175.835,71.5 176.435,71.5 176.435,70.3
no net on Bottom Paste "BOTTOMPASTE1149" (solid, pour order 0): 177.105,70.3 177.105,71.5 177.705,71.5 177.705,70.3
no net on Bottom Paste "BOTTOMPASTE1150" (solid, pour order 0): 175.7,67.05 175.7,68.25 177.355,68.25 177.355,67.05
no net on Bottom Paste "BOTTOMPASTE1151" (solid, pour order 0): 175.7,68.65 175.7,69.85 177.355,69.85 177.355,68.65
no net on Bottom Paste "BOTTOMPASTE1152" (solid, pour order 0): 173.645,68.65 173.645,69.85 175.3,69.85 175.3,68.65
no net on Bottom Paste "BOTTOMPASTE1153" (solid, pour order 0): 173.645,67.05 173.645,68.25 175.3,68.25 175.3,67.05
no net on Bottom Paste "BOTTOMPASTE1154" (solid, pour order 0): 182.565,64.5 182.565,65.7 183.165,65.7 183.165,64.5
no net on Bottom Paste "BOTTOMPASTE1155" (solid, pour order 0): 185.105,64.5 185.105,65.7 185.705,65.7 185.705,64.5
no net on Bottom Paste "BOTTOMPASTE1156" (solid, pour order 0): 181.295,70.3 181.295,71.5 181.895,71.5 181.895,70.3
no net on Bottom Paste "BOTTOMPASTE1157" (solid, pour order 0): 182.565,70.3 182.565,71.5 183.165,71.5 183.165,70.3
no net on Bottom Paste "BOTTOMPASTE1158" (solid, pour order 0): 183.835,70.3 183.835,71.5 184.435,71.5 184.435,70.3
no net on Bottom Paste "BOTTOMPASTE1159" (solid, pour order 0): 185.105,70.3 185.105,71.5 185.705,71.5 185.705,70.3
no net on Bottom Paste "BOTTOMPASTE1160" (solid, pour order 0): 183.7,67.05 183.7,68.25 185.355,68.25 185.355,67.05
no net on Bottom Paste "BOTTOMPASTE1161" (solid, pour order 0): 183.7,68.65 183.7,69.85 185.355,69.85 185.355,68.65
no net on Bottom Paste "BOTTOMPASTE1162" (solid, pour order 0): 181.645,68.65 181.645,69.85 183.3,69.85 183.3,68.65
no net on Bottom Paste "BOTTOMPASTE1163" (solid, pour order 0): 181.645,67.05 181.645,68.25 183.3,68.25 183.3,67.05
no net on Bottom Paste "BOTTOMPASTE1164" (solid, pour order 0): 190.565,64.5 190.565,65.7 191.165,65.7 191.165,64.5
no net on Bottom Paste "BOTTOMPASTE1165" (solid, pour order 0): 193.105,64.5 193.105,65.7 193.705,65.7 193.705,64.5
no net on Bottom Paste "BOTTOMPASTE1166" (solid, pour order 0): 189.295,70.3 189.295,71.5 189.895,71.5 189.895,70.3
no net on Bottom Paste "BOTTOMPASTE1167" (solid, pour order 0): 190.565,70.3 190.565,71.5 191.165,71.5 191.165,70.3
no net on Bottom Paste "BOTTOMPASTE1168" (solid, pour order 0): 191.835,70.3 191.835,71.5 192.435,71.5 192.435,70.3
no net on Bottom Paste "BOTTOMPASTE1169" (solid, pour order 0): 193.105,70.3 193.105,71.5 193.705,71.5 193.705,70.3
no net on Bottom Paste "BOTTOMPASTE1170" (solid, pour order 0): 191.7,67.05 191.7,68.25 193.355,68.25 193.355,67.05
no net on Bottom Paste "BOTTOMPASTE1171" (solid, pour order 0): 191.7,68.65 191.7,69.85 193.355,69.85 193.355,68.65
no net on Bottom Paste "BOTTOMPASTE1172" (solid, pour order 0): 189.645,68.65 189.645,69.85 191.3,69.85 191.3,68.65
no net on Bottom Paste "BOTTOMPASTE1173" (solid, pour order 0): 189.645,67.05 189.645,68.25 191.3,68.25 191.3,67.05
no net on Bottom Paste "BOTTOMPASTE1174" (solid, pour order 0): 174.565,54.5 174.565,55.7 175.165,55.7 175.165,54.5
no net on Bottom Paste "BOTTOMPASTE1175" (solid, pour order 0): 177.105,54.5 177.105,55.7 177.705,55.7 177.705,54.5
no net on Bottom Paste "BOTTOMPASTE1176" (solid, pour order 0): 173.295,60.3 173.295,61.5 173.895,61.5 173.895,60.3
no net on Bottom Paste "BOTTOMPASTE1177" (solid, pour order 0): 174.565,60.3 174.565,61.5 175.165,61.5 175.165,60.3
no net on Bottom Paste "BOTTOMPASTE1178" (solid, pour order 0): 175.835,60.3 175.835,61.5 176.435,61.5 176.435,60.3
no net on Bottom Paste "BOTTOMPASTE1179" (solid, pour order 0): 177.105,60.3 177.105,61.5 177.705,61.5 177.705,60.3
no net on Bottom Paste "BOTTOMPASTE1180" (solid, pour order 0): 175.7,57.05 175.7,58.25 177.355,58.25 177.355,57.05
no net on Bottom Paste "BOTTOMPASTE1181" (solid, pour order 0): 175.7,58.65 175.7,59.85 177.355,59.85 177.355,58.65
no net on Bottom Paste "BOTTOMPASTE1182" (solid, pour order 0): 173.645,58.65 173.645,59.85 175.3,59.85 175.3,58.65
no net on Bottom Paste "BOTTOMPASTE1183" (solid, pour order 0): 173.645,57.05 173.645,58.25 175.3,58.25 175.3,57.05
no net on Bottom Paste "BOTTOMPASTE1184" (solid, pour order 0): 182.565,54.5 182.565,55.7 183.165,55.7 183.165,54.5
no net on Bottom Paste "BOTTOMPASTE1185" (solid, pour order 0): 185.105,54.5 185.105,55.7 185.705,55.7 185.705,54.5
no net on Bottom Paste "BOTTOMPASTE1186" (solid, pour order 0): 181.295,60.3 181.295,61.5 181.895,61.5 181.895,60.3
no net on Bottom Paste "BOTTOMPASTE1187" (solid, pour order 0): 182.565,60.3 182.565,61.5 183.165,61.5 183.165,60.3
no net on Bottom Paste "BOTTOMPASTE1188" (solid, pour order 0): 183.835,60.3 183.835,61.5 184.435,61.5 184.435,60.3
no net on Bottom Paste "BOTTOMPASTE1189" (solid, pour order 0): 185.105,60.3 185.105,61.5 185.705,61.5 185.705,60.3
no net on Bottom Paste "BOTTOMPASTE1190" (solid, pour order 0): 183.7,57.05 183.7,58.25 185.355,58.25 185.355,57.05
no net on Bottom Paste "BOTTOMPASTE1191" (solid, pour order 0): 183.7,58.65 183.7,59.85 185.355,59.85 185.355,58.65
no net on Bottom Paste "BOTTOMPASTE1192" (solid, pour order 0): 181.645,58.65 181.645,59.85 183.3,59.85 183.3,58.65
no net on Bottom Paste "BOTTOMPASTE1193" (solid, pour order 0): 181.645,57.05 181.645,58.25 183.3,58.25 183.3,57.05
no net on Bottom Paste "BOTTOMPASTE1194" (solid, pour order 0): 190.565,54.5 190.565,55.7 191.165,55.7 191.165,54.5
no net on Bottom Paste "BOTTOMPASTE1195" (solid, pour order 0): 193.105,54.5 193.105,55.7 193.705,55.7 193.705,54.5
no net on Bottom Paste "BOTTOMPASTE1196" (solid, pour order 0): 189.295,60.3 189.295,61.5 189.895,61.5 189.895,60.3
no net on Bottom Paste "BOTTOMPASTE1197" (solid, pour order 0): 190.565,60.3 190.565,61.5 191.165,61.5 191.165,60.3
no net on Bottom Paste "BOTTOMPASTE1198" (solid, pour order 0): 191.835,60.3 191.835,61.5 192.435,61.5 192.435,60.3
no net on Bottom Paste "BOTTOMPASTE1199" (solid, pour order 0): 193.105,60.3 193.105,61.5 193.705,61.5 193.705,60.3
no net on Bottom Paste "BOTTOMPASTE1200" (solid, pour order 0): 191.7,57.05 191.7,58.25 193.355,58.25 193.355,57.05
no net on Bottom Paste "BOTTOMPASTE1201" (solid, pour order 0): 191.7,58.65 191.7,59.85 193.355,59.85 193.355,58.65
no net on Bottom Paste "BOTTOMPASTE1202" (solid, pour order 0): 189.645,58.65 189.645,59.85 191.3,59.85 191.3,58.65
no net on Bottom Paste "BOTTOMPASTE1203" (solid, pour order 0): 189.645,57.05 189.645,58.25 191.3,58.25 191.3,57.05
no net on Bottom Paste "BOTTOMPASTE1204" (solid, pour order 0): 50.55,255.565 50.55,256.165 51.75,256.165 51.75,255.565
